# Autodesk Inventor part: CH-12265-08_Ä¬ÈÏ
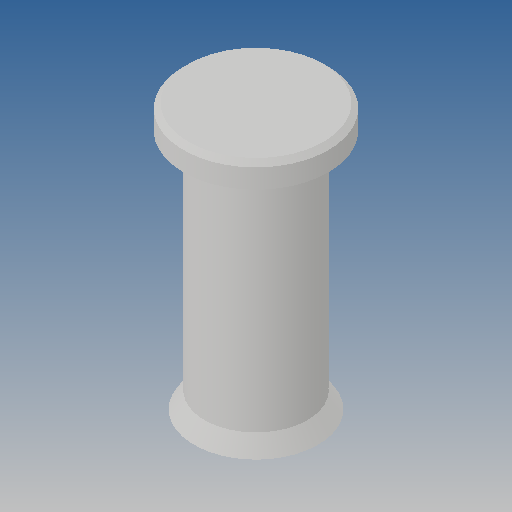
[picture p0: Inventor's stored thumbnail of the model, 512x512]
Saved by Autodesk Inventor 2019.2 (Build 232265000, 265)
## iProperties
Created: 2012-09
Part Number: CH-12265-08_Ä¬ÈÏ
Material: Ogólny
Document SubType Name: Modeling
Designer: CADENGINEERING4
Density: 1 g/cm^3
Appearance: Domyślna
Author: CADENGINEERING4
Revision Number: ÈÎºÎ
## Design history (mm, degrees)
feature "NONE"
node "Bryła1"
